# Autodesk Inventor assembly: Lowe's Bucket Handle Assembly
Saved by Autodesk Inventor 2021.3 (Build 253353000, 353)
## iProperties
Created: 2022-12
Part Number: Lowe's Bucket Handle Assembly
Document SubType Name: Assembly
Designer: AdminForWorker
Title: Lowe's Bucket Handle Assembly
Author: AdminForWorker
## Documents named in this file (3)
- c:\worker\convert-fusion-r07-cosv3\tmp\job-1\248\output\files\02726f4c-9815-42dc-95dc-176fb5068647\Lowe's Bucket Handle Assembly.iam
- c:\worker\convert-fusion-r07-cosv3\tmp\job-1\248\output\files\02726f4c-9815-42dc-95dc-176fb5068647\Lowe's Bucket Steel Handle.ipt
- c:\worker\convert-fusion-r07-cosv3\tmp\job-1\248\output\files\02726f4c-9815-42dc-95dc-176fb5068647\Lowe's Bucket Plastic Grip.ipt
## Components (2 placed, 2 different names)
1. Lowe's Bucket Steel Handle:1
2. Lowe's Bucket Plastic Grip:1
